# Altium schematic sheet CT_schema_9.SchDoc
size 254 x 194 mm
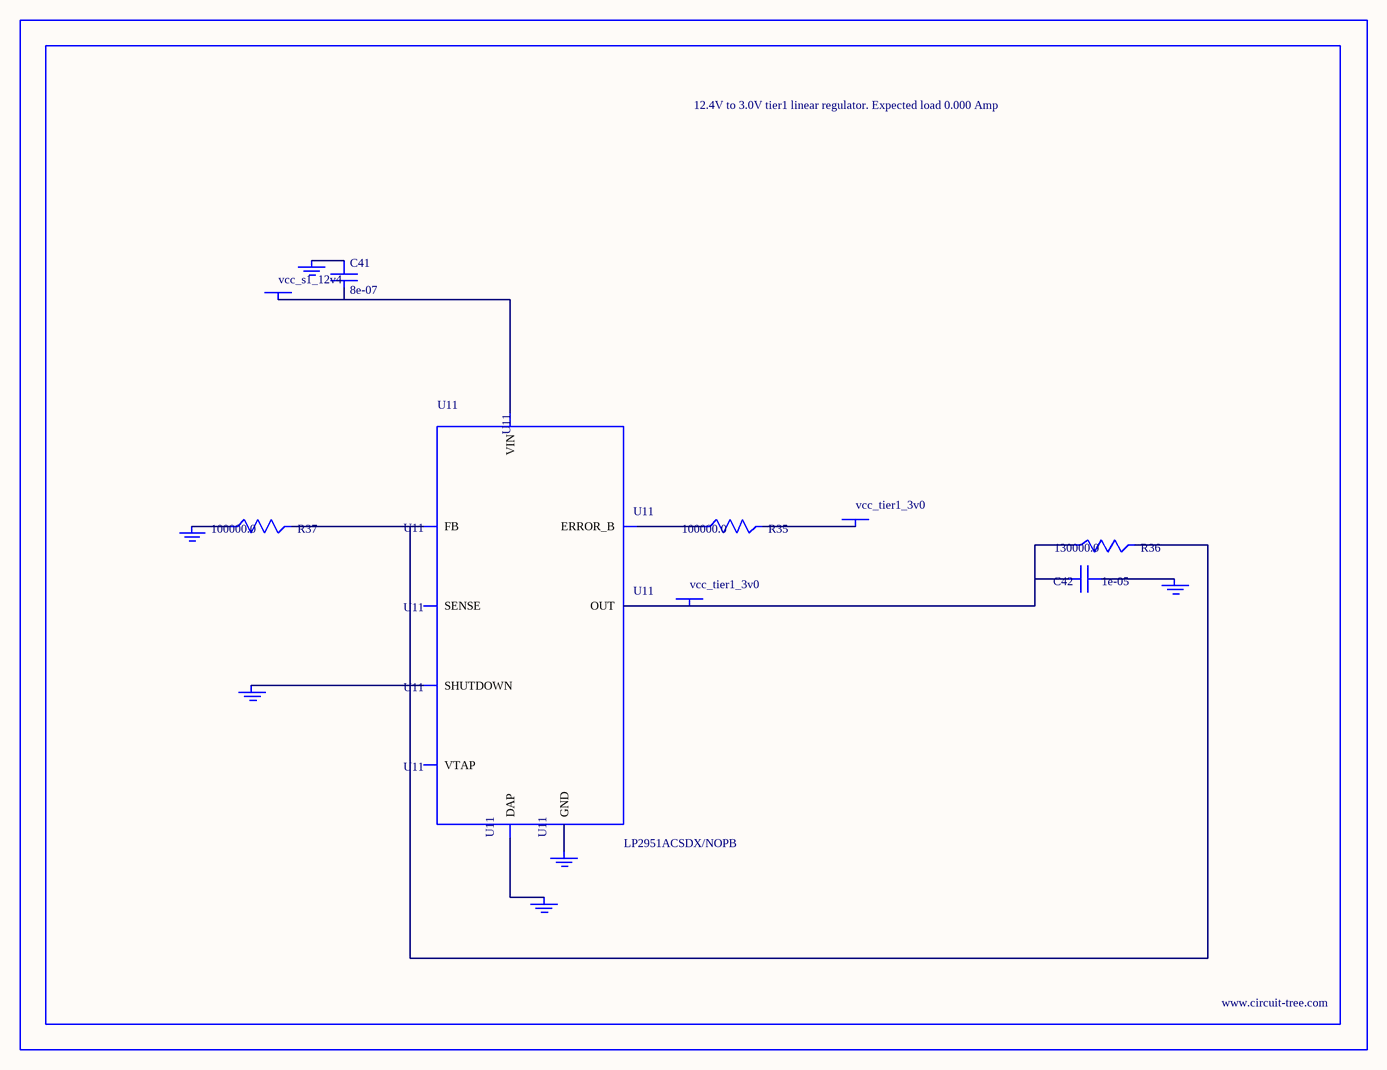
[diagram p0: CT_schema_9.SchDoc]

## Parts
BORDER8  (no value)
C41  8e-07  [R0603]
C42  1e-05  [C1210]
GND_INSTANCE_8_0  (no value)
GND_INSTANCE_8_1  (no value)
GND_INSTANCE_8_2  (no value)
GND_INSTANCE_8_3  (no value)
GND_INSTANCE_8_4  (no value)
GND_INSTANCE_8_5  (no value)
POWER_INSTANCE_8_0  vcc_tier1_3v0
POWER_INSTANCE_8_1  vcc_s1_12v4
POWER_INSTANCE_8_2  vcc_tier1_3v0
R35  100000.0  [R0603]
R36  130000.0  [R0603]
R37  100000.0  [R0603]
U11  LP2951ACSDX/NOPB  [WSON-8]

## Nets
NetC41_1: C41.1 GND_INSTANCE_8_3.0(GND)
NetC41_2: C41.2 POWER_INSTANCE_8_1.0(PWR) U11.8(VIN)
NetC42_1: C42.1 GND_INSTANCE_8_0.0(GND)
NetC42_2: C42.2 POWER_INSTANCE_8_2.0(PWR) R36.1 U11.1(OUT)
NetGND_INSTANCE_8_1_0: GND_INSTANCE_8_1.0(GND) U11.3(SHUTDOWN)
NetGND_INSTANCE_8_2_0: GND_INSTANCE_8_2.0(GND) R37.1
NetGND_INSTANCE_8_4_0: GND_INSTANCE_8_4.0(GND) U11.PAD(DAP)
NetGND_INSTANCE_8_5_0: GND_INSTANCE_8_5.0(GND) U11.4(GND)
NetPOWER_INSTANCE_8_0_0: POWER_INSTANCE_8_0.0(PWR) R35.2
NetR35_1: R35.1 U11.5(ERROR_B)
NetR36_2: R36.2 R37.2 U11.7(FB)

Not connected (* = marked no-connect by the designer): U11 2(SENSE) 6(VTAP)

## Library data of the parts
BORDER8 = BORDER_PAGE8
C41 = C41
C42 = GRM32DR61E106MA12L
GND_INSTANCE_8_0-GND_INSTANCE_8_5 = GND
POWER_INSTANCE_8_0-POWER_INSTANCE_8_2 = PWR
R35 R37 = RC0603JR-07100KL
R36 = RC0603JR-07130KL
